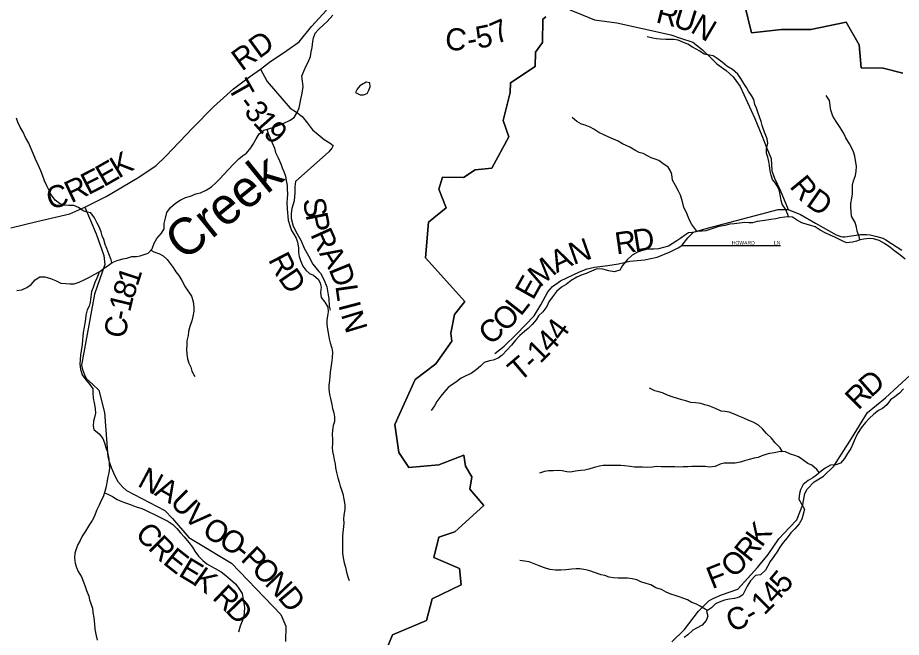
# Model space of a CAD drawing. Extents: x 1624196 to 2029251, y 146837 to 440034.
# Drawn here: x 1799187 to 1811228, y 279607 to 288051 of the extents above; entities that cross this region are included whole.
import ezdxf

# ---------------------------------------------------------------- set-up
doc = ezdxf.new("R2010")
doc.units = 0
for name, color, linetype in [('GM_X_County_Road', 7, 'Continuous'), ('GM_X_County_Road_Text', 7, 'Continuous'), ('GM_X_Minor_Lake', 7, 'Continuous'), ('GM_X_Minor_River', 7, 'Continuous'), ('GM_X_Minor_River_Text', 7, 'Continuous'), ('GM_X_Township', 7, 'Continuous'), ('GM_X_Township_Road', 7, 'Continuous'), ('GM_X_Township_Road_Text', 7, 'Continuous'), ('GM_X_Township_Subdivision', 7, 'Continuous'), ('GM_X_Township_Subdivision_Text', 7, 'Continuous')]:
    doc.layers.add(name, color=color, linetype=linetype)

msp = doc.modelspace()

# ---------------------------------------------------------------- linework, layer by layer
at = {"layer": 'GM_X_County_Road'}
for points in [[(1806564, 288322), (1806564, 288322), (1806598, 288221), (1806733, 288148), (1806814, 288116), (1807046, 288021), (1807350, 287981), (1807350, 287981)], [(1799095, 285185), (1799448, 285272), (1799899, 285377), (1800101, 285470), (1800394, 285615), (1800817, 285865), (1801069, 286034), (1801205, 286164), (1801575, 286551), (1801854, 286837), (1802127, 287083), (1802346, 287246), (1802498, 287348), (1802618, 287446), (1802856, 287603), (1803024, 287721), (1803192, 287930), (1803393, 288155)], [(1807350, 287981), (1807375, 287978), (1808086, 287819), (1808219, 287772), (1808385, 287719), (1808518, 287614), (1808642, 287493), (1808715, 287423), (1808843, 287332), (1808936, 287243), (1809034, 287111), (1809231, 286679), (1809326, 286445), (1809392, 286281), (1809454, 286133), (1809465, 285965), (1809499, 285863), (1809577, 285699), (1809684, 285437)], [(1800101, 285470), (1800256, 285104), (1800363, 284808), (1800374, 284689), (1800232, 284284), (1800058, 283316), (1800072, 283258), (1800097, 283185), (1800120, 283132), (1800211, 283051), (1800295, 282977), (1800368, 282669), (1800414, 282066), (1800428, 282014), (1800466, 281912), (1800493, 281850), (1800546, 281736), (1800584, 281694), (1800619, 281654), (1800668, 281609), (1801191, 281335), (1801299, 281224), (1801521, 280965), (1802103, 280617), (1802774, 279917), (1802842, 279757), (1802836, 279548)], [(1809684, 285437), (1809684, 285437), (1809853, 285370), (1810059, 285250), (1810339, 285090), (1810405, 285069), (1810429, 285065), (1810459, 285065), (1810672, 285097), (1810752, 285095), (1810805, 285090), (1810894, 285069), (1810974, 285046), (1811019, 285022), (1811235, 284882)], [(1808100, 279545), (1808275, 279714), (1808462, 279965), (1808607, 280103), (1808646, 280128), (1808675, 280140), (1808777, 280185), (1808998, 280264), (1809269, 280556), (1809412, 280734), (1809560, 280948), (1809702, 281102), (1809805, 281208), (1809886, 281419), (1809914, 281566), (1809946, 281627), (1810041, 281724), (1810167, 281802), (1810309, 281940), (1810548, 282318), (1810768, 282670), (1811012, 282869), (1811350, 283180)]]:
    msp.add_lwpolyline(points, dxfattribs=at)
at = {"layer": 'GM_X_Minor_Lake'}
for points in [[(1803914, 287160), (1803895, 287151), (1803851, 287121), (1803815, 287079), (1803792, 287033), (1803852, 286999)], [(1803852, 286999), (1803900, 287000), (1803949, 287020), (1803973, 287064), (1803991, 287108), (1803986, 287161), (1803935, 287171), (1803914, 287160)]]:
    msp.add_lwpolyline(points, dxfattribs=at)
at = {"layer": 'GM_X_Minor_River'}
for points in [[(1802435, 286400), (1802478, 286468), (1802542, 286520), (1802603, 286537), (1802679, 286559), (1802751, 286585), (1802816, 286614), (1802892, 286648), (1802955, 286692), (1803000, 286768), (1803024, 286822), (1803038, 286890), (1803047, 286942), (1803061, 286998), (1803070, 287048), (1803078, 287115), (1803067, 287187), (1803059, 287255), (1803085, 287323), (1803120, 287395), (1803146, 287447), (1803175, 287523), (1803188, 287584), (1803202, 287646), (1803209, 287726), (1803217, 287776), (1803239, 287842), (1803292, 287896), (1803353, 287952), (1803405, 288000), (1803480, 288087)], [(1809689, 285339), (1809682, 285371), (1809650, 285440), (1809605, 285510), (1809591, 285561), (1809581, 285615), (1809568, 285685), (1809550, 285735), (1809512, 285794), (1809472, 285844), (1809455, 285905), (1809439, 285961), (1809432, 286035), (1809424, 286093), (1809410, 286150), (1809389, 286206), (1809389, 286272), (1809408, 286342), (1809402, 286401), (1809374, 286467), (1809351, 286529), (1809331, 286582), (1809317, 286634), (1809295, 286698), (1809278, 286750), (1809254, 286817), (1809232, 286869), (1809217, 286937), (1809187, 286990), (1809147, 287048), (1809119, 287099), (1809082, 287153), (1809040, 287221), (1809000, 287282), (1808928, 287345), (1808850, 287389), (1808787, 287444), (1808717, 287496), (1808665, 287533), (1808613, 287539), (1808540, 287554), (1808484, 287596), (1808434, 287622), (1808382, 287649), (1808320, 287689), (1808260, 287714), (1808186, 287744), (1808126, 287755), (1808018, 287755), (1807944, 287758), (1807891, 287764), (1807841, 287772), (1807767, 287789)], [(1810662, 285021), (1810654, 285069), (1810626, 285143), (1810616, 285195), (1810599, 285262), (1810551, 285344), (1810545, 285410), (1810540, 285469), (1810540, 285521), (1810555, 285591), (1810561, 285649), (1810562, 285768), (1810576, 285828), (1810603, 285902), (1810613, 285960), (1810616, 286024), (1810593, 286165), (1810575, 286223), (1810553, 286273), (1810521, 286334), (1810474, 286412), (1810440, 286483), (1810384, 286567), (1810339, 286636), (1810295, 286710), (1810269, 286789), (1810260, 286855), (1810248, 286921), (1810205, 286990)], [(1800472, 284713), (1800461, 284750), (1800428, 284833), (1800402, 284907), (1800378, 284961), (1800361, 285026), (1800339, 285078), (1800325, 285132), (1800298, 285199), (1800270, 285249), (1800232, 285322), (1800183, 285392), (1800132, 285400), (1800080, 285419), (1800016, 285463), (1799952, 285490), (1799886, 285492), (1799814, 285497), (1799758, 285517), (1799698, 285566), (1799650, 285632), (1799616, 285694), (1799583, 285759), (1799551, 285829), (1799524, 285904), (1799502, 285964), (1799466, 286047), (1799431, 286125), (1799399, 286201), (1799369, 286264), (1799338, 286342), (1799294, 286419), (1799260, 286489), (1799221, 286558), (1799191, 286626), (1799169, 286680)], [(1808444, 285134), (1808428, 285158), (1808373, 285233), (1808345, 285283), (1808325, 285337), (1808301, 285394), (1808264, 285464), (1808252, 285522), (1808238, 285573), (1808221, 285633), (1808191, 285685), (1808149, 285762), (1808110, 285836), (1808102, 285913), (1808084, 285963), (1808053, 286013), (1807977, 286064), (1807923, 286106), (1807873, 286123), (1807819, 286143), (1807769, 286167), (1807709, 286198), (1807656, 286214), (1807598, 286247), (1807528, 286287), (1807428, 286332), (1807368, 286368), (1807304, 286395), (1807232, 286428), (1807182, 286452), (1807108, 286488), (1807040, 286531), (1806986, 286559), (1806920, 286588), (1806868, 286602), (1806808, 286637), (1806742, 286693)], [(1802583, 286532), (1802600, 286473), (1802654, 286347), (1802687, 286274), (1802701, 286216), (1802735, 286141), (1802772, 286059), (1802790, 286007), (1802812, 285954), (1802835, 285890), (1802847, 285834), (1802859, 285765), (1802860, 285715), (1802864, 285645), (1802861, 285589), (1802857, 285531), (1802858, 285448), (1802862, 285396), (1802870, 285342), (1802875, 285292), (1802897, 285217), (1802919, 285153), (1802950, 285099), (1802980, 285046), (1803002, 284990), (1803012, 284916), (1803015, 284853), (1803025, 284795), (1803040, 284741), (1803072, 284666), (1803112, 284610), (1803164, 284565), (1803220, 284541), (1803286, 284484), (1803311, 284432), (1803321, 284378), (1803315, 284308), (1803322, 284237), (1803374, 284173), (1803414, 284106), (1803419, 284042), (1803409, 283990), (1803400, 283930), (1803398, 283872), (1803408, 283805), (1803419, 283755), (1803433, 283675), (1803443, 283619), (1803468, 283546), (1803476, 283492), (1803473, 283416), (1803465, 283344), (1803456, 283279), (1803446, 283219), (1803440, 283163), (1803435, 283105), (1803425, 283041), (1803428, 282991), (1803434, 282916), (1803452, 282860), (1803467, 282780), (1803479, 282725), (1803495, 282665), (1803502, 282613), (1803502, 282549), (1803487, 282495), (1803475, 282430), (1803471, 282370), (1803478, 282308), (1803476, 282244), (1803473, 282194), (1803479, 282141), (1803489, 282079), (1803500, 282025), (1803512, 281969), (1803520, 281918), (1803531, 281852), (1803549, 281780), (1803569, 281719), (1803582, 281667), (1803598, 281617), (1803618, 281561), (1803633, 281490), (1803647, 281412), (1803643, 281348), (1803632, 281270), (1803628, 281219), (1803631, 281169), (1803629, 281115), (1803620, 281037), (1803612, 280985), (1803612, 280930), (1803613, 280872), (1803613, 280752), (1803622, 280688), (1803636, 280621), (1803655, 280561), (1803669, 280493), (1803685, 280430), (1803704, 280380)], [(1799174, 284331), (1799242, 284344), (1799313, 284372), (1799371, 284414), (1799426, 284478), (1799490, 284519), (1799559, 284521), (1799633, 284498), (1799701, 284468), (1799773, 284433), (1799843, 284427), (1799897, 284424), (1799957, 284424), (1800026, 284448), (1800102, 284483), (1800167, 284513), (1800231, 284551), (1800306, 284591), (1800370, 284640), (1800421, 284676), (1800473, 284714), (1800544, 284740), (1800620, 284765), (1800674, 284773), (1800741, 284797), (1800805, 284796), (1800857, 284806), (1800911, 284822), (1800964, 284842), (1801020, 284903), (1801045, 284978), (1801083, 285042), (1801146, 285115), (1801185, 285175), (1801185, 285244), (1801200, 285318), (1801220, 285394), (1801271, 285466), (1801337, 285522), (1801402, 285563), (1801472, 285599), (1801543, 285619), (1801617, 285652), (1801680, 285664), (1801756, 285702), (1801827, 285745), (1801885, 285799), (1801936, 285849), (1802002, 285919), (1802055, 285979), (1802128, 286055), (1802199, 286128), (1802251, 286170), (1802305, 286206), (1802366, 286276), (1802395, 286328), (1802435, 286400)], [(1811280, 284758), (1811206, 284817), (1811138, 284869), (1811070, 284924), (1810998, 284972), (1810928, 285013), (1810850, 285037), (1810788, 285040), (1810718, 285034), (1810667, 285022), (1810617, 285007), (1810563, 284991), (1810482, 284983), (1810432, 285006), (1810378, 285032), (1810324, 285061), (1810260, 285085), (1810190, 285118), (1810124, 285154), (1810052, 285199), (1809994, 285221), (1809944, 285231), (1809870, 285254), (1809800, 285296), (1809746, 285331), (1809692, 285339), (1809640, 285332), (1809573, 285324), (1809517, 285312), (1809451, 285301), (1809368, 285287), (1809264, 285272), (1809202, 285254), (1809150, 285254), (1809095, 285259), (1809023, 285251), (1808951, 285241), (1808892, 285238), (1808822, 285220), (1808740, 285204), (1808687, 285189), (1808617, 285165), (1808565, 285147), (1808515, 285140), (1808452, 285136), (1808384, 285124), (1808328, 285119), (1808273, 285081), (1808223, 285045), (1808170, 285011), (1808104, 284967), (1808054, 284936), (1807987, 284918), (1807917, 284902), (1807857, 284897), (1807806, 284897), (1807750, 284891), (1807700, 284878), (1807634, 284854), (1807559, 284816), (1807492, 284750), (1807430, 284672), (1807391, 284608), (1807317, 284587), (1807244, 284599), (1807194, 284614), (1807140, 284630), (1807068, 284622), (1807008, 284597), (1806933, 284563), (1806879, 284547), (1806808, 284516), (1806730, 284470), (1806659, 284416), (1806599, 284378), (1806528, 284321), (1806473, 284247), (1806425, 284179), (1806396, 284115)], [(1801003, 284884), (1801044, 284859), (1801120, 284833), (1801170, 284806), (1801222, 284754), (1801266, 284703), (1801306, 284645), (1801343, 284588), (1801383, 284536), (1801425, 284468), (1801471, 284385), (1801554, 284256), (1801580, 284184), (1801587, 284103), (1801587, 284053), (1801576, 283977), (1801562, 283919), (1801535, 283843), (1801517, 283773), (1801508, 283722), (1801494, 283646), (1801491, 283592), (1801489, 283534), (1801491, 283464), (1801502, 283401), (1801518, 283341), (1801546, 283287), (1801561, 283233), (1801603, 283162)], [(1800298, 284587), (1800294, 284569), (1800265, 284501), (1800237, 284441), (1800216, 284374), (1800194, 284318), (1800185, 284246), (1800173, 284172), (1800160, 284120), (1800136, 284068), (1800115, 283998), (1800111, 283940), (1800104, 283889), (1800092, 283835), (1800078, 283763), (1800075, 283713), (1800069, 283657), (1800064, 283599), (1800052, 283512), (1800045, 283454), (1800037, 283392), (1800035, 283328), (1800044, 283262), (1800066, 283185), (1800117, 283115), (1800169, 283052), (1800213, 282992), (1800211, 282938), (1800214, 282867), (1800228, 282801), (1800241, 282727), (1800247, 282660), (1800233, 282604), (1800222, 282552), (1800216, 282488), (1800225, 282438), (1800297, 282381), (1800347, 282315), (1800369, 282258), (1800390, 282194), (1800408, 282142), (1800422, 282089), (1800428, 282033), (1800435, 281963), (1800437, 281911), (1800428, 281849), (1800416, 281792), (1800403, 281716), (1800391, 281664), (1800374, 281592), (1800350, 281522), (1800326, 281472), (1800297, 281406), (1800260, 281334), (1800234, 281258), (1800201, 281200), (1800165, 281144), (1800110, 281052), (1800067, 280984), (1800037, 280926), (1800006, 280870), (1799990, 280820), (1799966, 280754), (1799961, 280691), (1799969, 280615), (1799990, 280559), (1800012, 280505), (1800056, 280430), (1800080, 280372), (1800101, 280311), (1800125, 280245), (1800158, 280167), (1800168, 280116), (1800206, 280002), (1800213, 279945), (1800223, 279873), (1800232, 279787), (1800240, 279717), (1800257, 279628), (1800271, 279570)], [(1806396, 284115), (1806342, 284041), (1806285, 283987), (1806251, 283935), (1806198, 283869), (1806141, 283815), (1806091, 283773), (1806030, 283722), (1805972, 283654), (1805915, 283586), (1805855, 283524), (1805788, 283454), (1805735, 283412), (1805667, 283385), (1805615, 283373), (1805544, 283353), (1805492, 283303), (1805435, 283253), (1805365, 283200), (1805294, 283172), (1805228, 283138), (1805155, 283081), (1805105, 283049), (1805054, 283009), (1804994, 282945), (1804953, 282893), (1804899, 282821), (1804866, 282763), (1804820, 282697)], [(1809611, 282136), (1809579, 282187), (1809509, 282258), (1809459, 282320), (1809392, 282385), (1809338, 282448), (1809282, 282500), (1809210, 282541), (1809148, 282563), (1809082, 282592), (1809012, 282622), (1808962, 282645), (1808880, 282673), (1808828, 282683), (1808773, 282690), (1808695, 282726), (1808603, 282763), (1808551, 282777), (1808497, 282794), (1808425, 282800), (1808359, 282809), (1808291, 282831), (1808235, 282844), (1808178, 282860), (1808104, 282884), (1808040, 282907), (1807972, 282937), (1807922, 282952), (1807868, 282964), (1807796, 283003)], [(1811258, 282992), (1811202, 282934), (1811139, 282886), (1811081, 282843), (1811030, 282775), (1810971, 282725), (1810919, 282699), (1810855, 282649), (1810790, 282588), (1810741, 282532), (1810681, 282460), (1810632, 282386), (1810599, 282314), (1810571, 282254), (1810540, 282182), (1810494, 282112), (1810455, 282044), (1810401, 281978), (1810334, 281958), (1810262, 281954), (1810189, 281913), (1810137, 281869), (1810074, 281817), (1810022, 281781), (1809957, 281742), (1809891, 281688), (1809852, 281618), (1809840, 281566), (1809831, 281489), (1809871, 281419), (1809907, 281351), (1809888, 281266), (1809872, 281216), (1809835, 281154), (1809777, 281084), (1809724, 281031), (1809671, 280963), (1809617, 280901), (1809574, 280835), (1809540, 280781), (1809489, 280709), (1809442, 280639), (1809406, 280573), (1809375, 280521), (1809307, 280459), (1809241, 280451), (1809172, 280376), (1809129, 280306), (1809101, 280250), (1809070, 280186), (1809020, 280156), (1808955, 280136), (1808885, 280128), (1808817, 280115), (1808748, 280087), (1808698, 280065), (1808640, 280010), (1808575, 279962), (1808591, 279893), (1808570, 279837), (1808514, 279771), (1808439, 279730)], [(1810113, 281849), (1810077, 281893), (1810009, 281952), (1809955, 281976), (1809887, 282027), (1809825, 282067), (1809775, 282086), (1809719, 282102), (1809649, 282133), (1809575, 282139), (1809498, 282120), (1809432, 282112), (1809382, 282100), (1809329, 282080), (1809277, 282059), (1809225, 282047), (1809155, 282029), (1809090, 282014), (1809030, 281992), (1808966, 281980), (1808891, 281979), (1808815, 281979), (1808761, 281967), (1808690, 281934), (1808616, 281926), (1808554, 281933), (1808504, 281933), (1808427, 281935), (1808375, 281936), (1808319, 281932), (1808255, 281930), (1808190, 281925), (1808140, 281929), (1808090, 281929), (1808012, 281932), (1807954, 281932), (1807897, 281934), (1807835, 281927), (1807763, 281919), (1807703, 281924), (1807648, 281924), (1807592, 281926), (1807532, 281933), (1807456, 281945), (1807404, 281949), (1807354, 281946), (1807235, 281946), (1807167, 281949), (1807113, 281941), (1807044, 281921), (1806970, 281900), (1806914, 281886), (1806859, 281880), (1806789, 281873), (1806719, 281859), (1806669, 281863), (1806608, 281874), (1806558, 281878), (1806486, 281877), (1806420, 281877), (1806364, 281867), (1806299, 281846)], [(1800369, 281575), (1800416, 281558), (1800478, 281527), (1800542, 281485), (1800608, 281456), (1800669, 281434), (1800735, 281411), (1800801, 281387), (1800879, 281364), (1800931, 281338), (1800983, 281313), (1801041, 281287), (1801105, 281253), (1801159, 281226), (1801231, 281190), (1801301, 281145), (1801355, 281091), (1801405, 281032), (1801458, 280978), (1801518, 280901), (1801568, 280836), (1801602, 280782), (1801649, 280713), (1801709, 280655), (1801763, 280610), (1801829, 280572), (1801879, 280546), (1801959, 280501), (1802025, 280450), (1802089, 280394), (1802159, 280331), (1802210, 280257), (1802244, 280202), (1802256, 280148), (1802269, 280068), (1802277, 280013), (1802275, 279943), (1802268, 279893), (1802248, 279829), (1802221, 279759), (1802195, 279679)], [(1808590, 279973), (1808555, 279990), (1808485, 280033), (1808435, 280059), (1808373, 280081), (1808313, 280116), (1808251, 280138), (1808201, 280159), (1808147, 280177), (1808085, 280197), (1808025, 280224), (1807959, 280258), (1807883, 280283), (1807813, 280321), (1807753, 280342), (1807678, 280364), (1807626, 280389), (1807560, 280405), (1807498, 280414), (1807446, 280414), (1807370, 280412), (1807307, 280419), (1807249, 280427), (1807189, 280448), (1807137, 280460), (1807049, 280489), (1806983, 280513), (1806927, 280527), (1806849, 280538), (1806796, 280538), (1806740, 280535), (1806658, 280525), (1806588, 280523), (1806517, 280524), (1806437, 280532), (1806367, 280555), (1806293, 280579), (1806227, 280606), (1806157, 280634), (1806029, 280655)], [(1808439, 279730), (1808385, 279702), (1808320, 279642), (1808270, 279606)]]:
    msp.add_lwpolyline(points, dxfattribs=at)
at = {"layer": 'GM_X_Township'}
for points in [[(1811250, 287297), (1810982, 287364), (1810682, 287366), (1810655, 287682), (1810477, 287992), (1809994, 287890), (1809594, 287891), (1809186, 287843), (1809093, 288234)], [(1809093, 288234), (1809186, 287843), (1809594, 287891), (1809994, 287890), (1810477, 287992), (1810655, 287682), (1810682, 287366), (1810982, 287364), (1811250, 287297)], [(1806382, 288063), (1806342, 288033), (1806339, 287714), (1806241, 287582), (1806238, 287385), (1805901, 287162), (1805898, 287032), (1805804, 286649), (1805879, 286427), (1805648, 285999), (1805421, 285976), (1805261, 285875), (1804978, 285877), (1804927, 285715), (1805027, 285461), (1804783, 285265), (1804746, 284777), (1805280, 284182), (1805140, 284007), (1805088, 283750), (1805105, 283643), (1804885, 283335), (1804602, 283122), (1804326, 282507), (1804379, 282125), (1804516, 281921), (1804926, 281958), (1805265, 282090), (1805290, 281937), (1805377, 281792), (1805349, 281625), (1805541, 281405), (1805146, 281042), (1804926, 280973), (1804858, 280696), (1805206, 280545), (1805232, 280324), (1804835, 280130), (1804757, 279837), (1804293, 279641), (1804145, 279275)], [(1804145, 279275), (1804293, 279641), (1804757, 279837), (1804835, 280130), (1805232, 280324), (1805206, 280545), (1804858, 280696), (1804926, 280973), (1805146, 281042), (1805541, 281405), (1805349, 281625), (1805377, 281792), (1805290, 281937), (1805265, 282090), (1804926, 281958), (1804516, 281921), (1804379, 282125), (1804326, 282507), (1804602, 283122), (1804885, 283335), (1805105, 283643), (1805088, 283750), (1805140, 284007), (1805280, 284182), (1804746, 284777), (1804783, 285265), (1805027, 285461), (1804927, 285715), (1804978, 285877), (1805261, 285875), (1805421, 285976), (1805648, 285999), (1805879, 286427), (1805804, 286649), (1805898, 287032), (1805901, 287162), (1806238, 287385), (1806241, 287582), (1806339, 287714), (1806342, 288033), (1806382, 288063)]]:
    msp.add_lwpolyline(points, dxfattribs=at)
at = {"layer": 'GM_X_Township_Road'}
for points in [[(1802498, 287348), (1802586, 287182), (1802900, 286816), (1802985, 286765), (1803064, 286703), (1803135, 286615), (1803204, 286524), (1803283, 286458), (1803362, 286391), (1803443, 286341), (1803486, 286310), (1803470, 286273), (1803428, 286223), (1802974, 285818), (1802964, 285744), (1802965, 285668), (1802956, 285553), (1802925, 285452), (1802916, 285384), (1802912, 285314), (1802943, 285209), (1802995, 285105), (1803050, 285008), (1803093, 284908), (1803148, 284804), (1803210, 284690), (1803289, 284592), (1803314, 284570), (1803359, 284483), (1803398, 284382), (1803428, 284220), (1803431, 284120), (1803447, 284064)], [(1805691, 283476), (1805817, 283575), (1805986, 283738), (1806225, 283989), (1806314, 284137), (1806409, 284313), (1806477, 284387), (1806584, 284463), (1806842, 284586), (1806949, 284627), (1807047, 284653), (1807230, 284674), (1807372, 284698), (1807527, 284734), (1807730, 284750), (1807902, 284788), (1808077, 284862), (1808189, 284916), (1808237, 284948), (1808243, 284952), (1808320, 285053), (1808396, 285130), (1808570, 285178), (1809224, 285352), (1809551, 285435), (1809684, 285437)]]:
    msp.add_lwpolyline(points, dxfattribs=at)
at = {"layer": 'GM_X_Township_Subdivision'}
msp.add_lwpolyline([(1808237, 284948), (1809581, 284947)], dxfattribs=at)

# ---------------------------------------------------------------- texts
at = {"layer": 'GM_X_County_Road_Text'}
for s, rotation, p in [('R', 346.1143, (1807870, 287990)), ('U', 342.739, (1808104, 287932)), ('7', 23.7594, (1805710, 287684)), ('N', 329.4273, (1808340, 287861)), ('C', 355.4522, (1805003, 287619)), ('5', 11.038, (1805459, 287627)), ('RD', 35.9872, (1802242, 287314)), ('-', 10.4604, (1805335, 287604)), ('K', 31.0042, (1800562, 285853)), ('E', 29.7429, (1800361, 285738)), ('E', 27.0881, (1800148, 285628)), ('R', 25.1949, (1799916, 285519)), ('R', 309.3913, (1809695, 285748)), ('C', 15.1031, (1799624, 285435)), ('D', 325.0247, (1809915, 285498)), ('1', 71.7403, (1800819, 284379)), ('8', 71.4317, (1800759, 284202)), ('1', 76.4964, (1800718, 284029)), ('-', 78.9243, (1800695, 283911)), ('C', 79.8735, (1800652, 283670)), ('D', 41.3902, (1810813, 282865)), ('R', 45.2663, (1810643, 282693)), ('N', 332.0648, (1800806, 281674)), ('A', 330.2255, (1801037, 281552)), ('U', 314.9189, (1801249, 281433)), ('V', 314.3844, (1801435, 281247)), ('O', 328.9856, (1801685, 281007)), ('K', 54.1143, (1809326, 280822)), ('C', 313.123, (1800774, 281003)), ('O', 327.1718, (1801909, 280872)), ('R', 315.3161, (1800951, 280814)), ('R', 51.1272, (1809161, 280616)), ('E', 321.5602, (1801153, 280617)), ('-', 320.8221, (1802124, 280734)), ('P', 315.9021, (1802214, 280661)), ('E', 329.0176, (1801364, 280453)), ('O', 43.8788, (1808943, 280403)), ('K', 324.6063, (1801551, 280341)), ('O', 313.7519, (1802358, 280522)), ('F', 21.6227, (1808649, 280260)), ('N', 313.6669, (1802540, 280331)), ('5', 50.0097, (1809635, 280187)), ('R', 316.3842, (1801827, 280135)), ('4', 47.5598, (1809501, 280041)), ('D', 310.1038, (1802719, 280144)), ('1', 44.9345, (1809360, 279899)), ('D', 314.1616, (1802003, 279967)), ('C', 21.5771, (1808913, 279674)), ('-', 29.9077, (1809185, 279786))]:
    msp.add_text(s, height=300, rotation=rotation, dxfattribs=at).set_placement(p)
at = {"layer": 'GM_X_Minor_River_Text'}
msp.add_text('Creek', height=500, rotation=39.0015, dxfattribs=at).set_placement((1801454, 284724))
at = {"layer": 'GM_X_Township_Road_Text'}
for s, rotation, p in [('T', 299.376, (1802040, 287106)), ('-', 307.4986, (1802176, 286872)), ('3', 310.1459, (1802260, 286763)), ('1', 311.4843, (1802384, 286615)), ('9', 315.4163, (1802522, 286461)), ('S', 280.0677, (1803071, 285572)), ('P', 281.5029, (1803108, 285365)), ('R', 294.0987, (1803170, 285098)), ('R', 8.0352, (1807347, 284823)), ('D', 9.191, (1807597, 284858)), ('N', 19.3911, (1806760, 284679)), ('A', 301.2296, (1803290, 284837)), ('A', 25.8873, (1806531, 284567)), ('R', 297.2039, (1802595, 284754)), ('M', 41.0098, (1806302, 284365)), ('D', 292.0544, (1803421, 284623)), ('D', 304.3492, (1802728, 284501)), ('E', 60.6181, (1806209, 284190)), ('L', 278.1834, (1803515, 284396)), ('I', 284.6527, (1803554, 284138)), ('L', 51.831, (1806043, 283972)), ('N', 286.9456, (1803589, 284006)), ('O', 45.4581, (1805834, 283756)), ('C', 40.912, (1805628, 283577)), ('4', 53.81, (1806595, 283629)), ('4', 46.8303, (1806443, 283464)), ('1', 45.4066, (1806308, 283326)), ('T', 40.3022, (1806026, 283077)), ('-', 43.573, (1806211, 283234))]:
    msp.add_text(s, height=300, rotation=rotation, dxfattribs=at).set_placement(p)
at = {"layer": 'GM_X_Township_Subdivision_Text'}
for s, p in [('HOWARD', (1808917, 284958)), ('LN', (1809493, 284958))]:
    msp.add_text(s, height=50, rotation=0, dxfattribs=at).set_placement(p)

doc.saveas('drawing.dxf')
